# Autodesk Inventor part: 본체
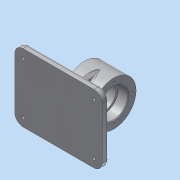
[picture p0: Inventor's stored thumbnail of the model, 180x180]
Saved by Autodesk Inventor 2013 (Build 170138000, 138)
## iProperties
Created: 2019-09
Part Number: 본체
Material: 알루미늄 6061
Document SubType Name: Modeling
Designer: Administrator
Density: 2.71 g/cm^3
Mass: 556.668 g
Surface Area: 495.884 cm^2
Volume: 205.413 cm^3
Author: Administrator
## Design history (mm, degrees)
sketch "스케치1"
  geometry: L1 (-59, 62)-(-50, 62); L2 (-50, 62)-(-50, -36); L3 (-50, -36)-(-59, -36); L4 (-59, -36)-(-59, 62); C1 r 32 at (0, 0); 1 further point
  constraints: 8 end point, 2 parallel, 1 centre point, 1 coincident, 1 horizontal, 1 perpendicular
  dimensions: "d0" = 64 diameter of C1; "d1" = 9 distance of L2.end L3.end; "d2" = 98 distance of L1.end L2.end; "d3" = 36 distance from line of L3 point (0, 0); "d4" = 59 distance from line of L4 point (0, 0)
extrude "돌출1" new body sketch "스케치1" stored distance "d5" = 42; taper "d6" = 0 deg
extrude "돌출2" join sketch "스케치1" stored distance "d7" = 126; taper "d8" = 0 deg
fillet "모깎기1" dims "d9" = 12
fillet "모깎기2" dims "d10" = 3
sketch "스케치2"
  geometry: L1 (0, 0)-(102, 0) reference; L2 (34, -29)-(68, -29); L3 (68, -29)-(68, -37); L4 (68, -37)-(34, -37); L5 (34, -37)-(34, -29); L6 (34, -33)-(68, -33); L7 (0, -95)-(102, -95) reference; 5 further points
  constraints: 10 end point, 5 midpoint, 2 parallel, 1 horizontal, 1 perpendicular, 1 vertical alignment
  dimensions: "d11" = 62 distance between parallel lines of L7 L6; "d12" = 8 distance of L4.end L2.start; "d13" = 34 distance between parallel lines of L3 L5
extrude "돌출3" join sketch "스케치2" stored distance "d16" = 126; taper "d17" = 0 deg
sketch "스케치3"
  geometry: L1 (55, -1)-(47, -1); L2 (47, -1)-(47, -65); L3 (47, -65)-(55, -65); L4 (55, -65)-(55, -1); L5 (55, -1)-(47, -65); L6 (47, -1)-(55, -65); 1 further point
  constraints: 12 end point, 2 midpoint, 2 parallel, 1 horizontal, 1 perpendicular
  dimensions: "d18" = 8 distance of L3.end L2.end; "d19" = 64 distance of L2.end L1.end
extrude "돌출4" join sketch "스케치3" stored distance "d20" = 126; taper "d21" = 0 deg
fillet "모깎기3" dims "d22" = 3
fillet "모깎기4" dims "d23" = 3
hole "구멍1" diameter "d26" = 42; stored, may be unused: countersink angle "d30" = 90 deg, drill point angle "d32" = 0 deg; dims "d24" = 10, "d25" = 10, "d27" = 6, "d28" = 4, "d29" = 2, "d31" = 15
hole "구멍2" diameter "d35" = 36; stored, may be unused: countersink angle "d39" = 90 deg, drill point angle "d41" = 0 deg; dims "d33" = 10, "d34" = 10, "d36" = 6, "d37" = 4, "d38" = 2, "d40" = 15
fillet "모깎기5" dims "d42" = 0.3
chamfer "모따기1" distance "d43" = 1; stored, may be unused: second distance "d44" = 2, angle "d45" = 45 deg
chamfer "모따기2" distance "d46" = 1; stored, may be unused: second distance "d47" = 2, angle "d48" = 45 deg
sketch "스케치4"
  geometry: C1 r 32 at (0, 0) reference; 1 further point
  constraints: 1 vertical alignment
  dimensions: "d49" = 26 distance of C1.centre point (0, 26)
hole "구멍3" sketch "스케치4" at (0, 26) diameter "d50" = 3.242; stored, may be unused: countersink angle "d54" = 90 deg, drill point angle "d56" = 118 deg; dims "d51" = 8, "d52" = 4, "d53" = 2, "d55" = 10
node "작업 평면1"
sketch "스케치5"
  geometry: L1 (-12, 83)-(-12, 9) reference; L2 (0, -3)-(102, -3) reference; 2 further points
  constraints: 1 other
  dimensions: "d60" = 63 distance from line of point (51, 7) L1; "d61" = 10 distance from line of L2 point (51, 7)
feature "엠보싱1" sketch "스케치5" dims "d1" = 9, "d2" = 98, "d3" = 36, "d4" = 59, "d9" = 12, "d62" = 0.5, "d63" = 0
sketch "스케치6"
  geometry: A1 r 9 centre (0, 83) between (0, 92) and (-9, 83) reference; A2 r 9 centre (0, 9) between (-9, 9) and (0, 0) reference; A3 r 9 centre (102, 9) between (102, 0) and (111, 9) reference; A4 r 9 centre (102, 83) between (111, 83) and (102, 92) reference; 5 further points
  constraints: 4 coincident
hole "구멍4" sketch "스케치6" at (0, 9), (102, 9), (102, 83), (0, 83) diameter "d64" = 4.5; stored, may be unused: countersink angle "d68" = 90 deg, drill point angle "d70" = 0 deg; dims "d65" = 6, "d66" = 8, "d67" = 4.4, "d69" = 8
node "솔리드1"
mirror "대칭1"
pattern_circular "원형 패턴1" dims angle "d58" = 360 deg
mirror "대칭2"
